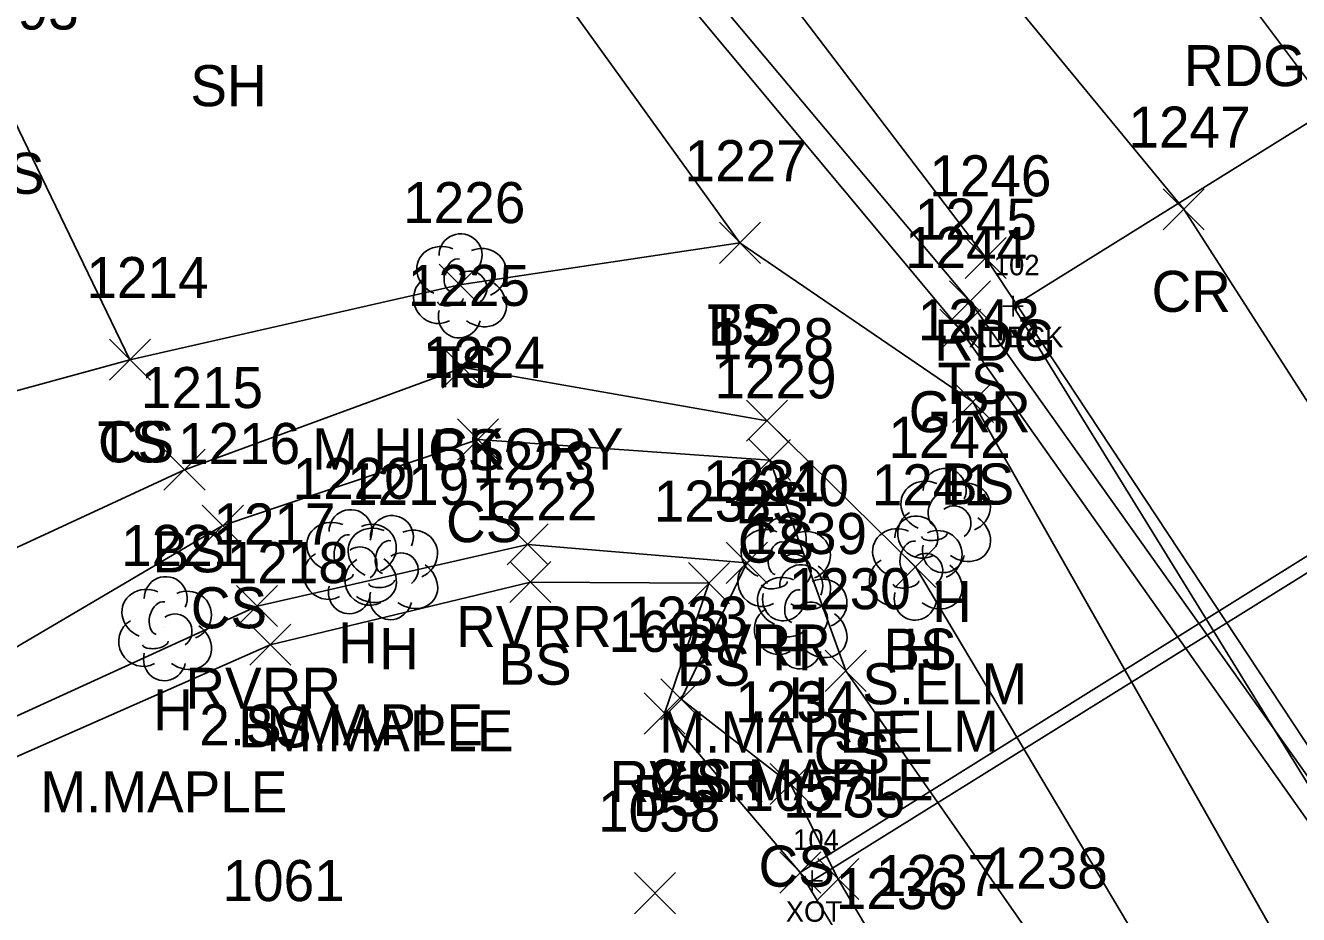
# Model space of a CAD drawing. Extents: x 1469310 to 1475157, y 493997 to 498873.
# Drawn here: x 1469498.4 to 1469560.4, y 498562.2 to 498605.4 of the extents above; entities that cross this region are included whole.
import ezdxf

# ---------------------------------------------------------------- set-up
doc = ezdxf.new("R2010")
doc.units = 0
for name, color, linetype in [('B_A', 7, 'Continuous'), ('B_I', 7, 'Continuous'), ('B_TIC', 7, 'Continuous'), ('BDEFAULT', 7, 'Continuous'), ('BELB', 7, 'Continuous'), ('D_I', 7, 'Continuous'), ('D_TIC', 7, 'Continuous'), ('DCP', 7, 'Continuous'), ('L_A', 7, 'Continuous'), ('L_C', 7, 'Continuous'), ('L_I', 7, 'Continuous'), ('L_TIC', 7, 'Continuous'), ('LAWE', 7, 'Continuous'), ('LELB', 7, 'Continuous'), ('LTD', 7, 'Continuous'), ('P_A', 7, 'Continuous'), ('P_I', 7, 'Continuous'), ('P_TIC', 7, 'Continuous'), ('PEU', 7, 'Continuous'), ('PRC', 7, 'Continuous'), ('R_A', 7, 'Continuous'), ('R_I', 7, 'Continuous'), ('R_TIC', 7, 'Continuous'), ('RGR', 7, 'Continuous')]:
    doc.layers.add(name, color=color, linetype=linetype)

msp = doc.modelspace()

# ---------------------------------------------------------------- linework, layer by layer
at = {"layer": 'B_TIC'}
for p, q in [((1469546.473, 498591.781), (1469546.549, 498591.781)), ((1469536.7, 498563.801), (1469536.776, 498563.801))]:
    msp.add_line(p, q, dxfattribs=at)
for points in [[(1469546.47, 498591.281), (1469546.47, 498592.281)], [(1469545.97, 498591.781), (1469546.97, 498591.781)], [(1469536.697, 498563.301), (1469536.697, 498564.301)], [(1469536.197, 498563.801), (1469537.197, 498563.801)]]:
    msp.add_lwpolyline(points, dxfattribs=at)
at = {"layer": 'BDEFAULT'}
msp.add_lwpolyline([(1469536.697, 498563.801), (1469602.369, 498604.653)], dxfattribs=at)
at = {"layer": 'BELB'}
msp.add_lwpolyline([(1469588.085, 498573.469), (1469568.345, 498605.383), (1469546.47, 498591.781), (1469566.105, 498559.964), (1469588.085, 498573.469)], dxfattribs=at)
at = {"layer": 'D_TIC'}
for points in [[(1469535.113, 498563.2), (1469537.113, 498565.2)], [(1469537.113, 498563.2), (1469535.113, 498565.2)]]:
    msp.add_lwpolyline(points, dxfattribs=at)
at = {"layer": 'DCP'}
msp.add_lwpolyline([(1469602.07, 498605.375), (1469536.113, 498564.2)], dxfattribs=at)
at = {"layer": 'L_TIC'}
for points in [[(1469532.172, 498593.862), (1469534.172, 498595.862)], [(1469534.172, 498593.862), (1469532.172, 498595.862)], [(1469532.172, 498593.862), (1469534.172, 498595.862)], [(1469534.172, 498593.862), (1469532.172, 498595.862)], [(1469518.522, 498591.822), (1469520.522, 498593.822)], [(1469520.522, 498591.822), (1469518.522, 498593.822)], [(1469543.375, 498591.02), (1469545.375, 498593.02)], [(1469545.375, 498591.02), (1469543.375, 498593.02)], [(1469502.469, 498588.172), (1469504.469, 498590.172)], [(1469504.469, 498588.172), (1469502.469, 498590.172)], [(1469502.469, 498588.172), (1469504.469, 498590.172)], [(1469504.469, 498588.172), (1469502.469, 498590.172)], [(1469518.691, 498587.789), (1469520.691, 498589.789)], [(1469520.691, 498587.789), (1469518.691, 498589.789)], [(1469543.52, 498586.119), (1469545.52, 498588.119)], [(1469545.52, 498586.119), (1469543.52, 498588.119)], [(1469533.493, 498585.197), (1469535.493, 498587.197)], [(1469535.493, 498585.197), (1469533.493, 498587.197)], [(1469519.418, 498584.286), (1469521.418, 498586.286)], [(1469521.418, 498584.286), (1469519.418, 498586.286)], [(1469533.627, 498583.287), (1469535.627, 498585.287)], [(1469535.627, 498583.287), (1469533.627, 498585.287)], [(1469505.126, 498582.816), (1469507.126, 498584.816)], [(1469507.126, 498582.816), (1469505.126, 498584.816)], [(1469506.99, 498580.091), (1469508.99, 498582.091)], [(1469508.99, 498580.091), (1469506.99, 498582.091)], [(1469521.838, 498579.179), (1469523.838, 498581.179)], [(1469523.838, 498579.179), (1469521.838, 498581.179)], [(1469532.507, 498578.279), (1469534.507, 498580.279)], [(1469534.507, 498578.279), (1469532.507, 498580.279)], [(1469540.719, 498578.078), (1469542.719, 498580.078)], [(1469542.719, 498578.078), (1469540.719, 498580.078)], [(1469521.971, 498577.343), (1469523.971, 498579.343)], [(1469523.971, 498577.343), (1469521.971, 498579.343)], [(1469530.664, 498577.288), (1469532.664, 498579.288)], [(1469532.664, 498577.288), (1469530.664, 498579.288)], [(1469508.656, 498576.171), (1469510.656, 498578.171)], [(1469510.656, 498576.171), (1469508.656, 498578.171)], [(1469509.304, 498574.289), (1469511.304, 498576.289)], [(1469511.304, 498574.289), (1469509.304, 498576.289)], [(1469537.322, 498573.02), (1469539.322, 498575.02)], [(1469539.322, 498573.02), (1469537.322, 498575.02)], [(1469529.314, 498571.636), (1469531.314, 498573.636)], [(1469531.314, 498571.636), (1469529.314, 498573.636)], [(1469529.314, 498571.636), (1469531.314, 498573.636)], [(1469531.314, 498571.636), (1469529.314, 498573.636)], [(1469528.504, 498570.943), (1469530.504, 498572.943)], [(1469530.504, 498570.943), (1469528.504, 498572.943)], [(1469534.638, 498567.508), (1469536.638, 498569.508)], [(1469536.638, 498567.508), (1469534.638, 498569.508)], [(1469535.113, 498563.2), (1469537.113, 498565.2)], [(1469537.113, 498563.2), (1469535.113, 498565.2)], [(1469536.962, 498562.876), (1469538.962, 498564.876)], [(1469538.962, 498562.876), (1469536.962, 498564.876)], [(1469528.036, 498562.191), (1469530.036, 498564.191)], [(1469530.036, 498562.191), (1469528.036, 498564.191)]]:
    msp.add_lwpolyline(points, dxfattribs=at)
at = {"layer": 'LAWE'}
msp.add_lwpolyline([(1469389.723, 498705.758), (1469405.142, 498682.895), (1469430.854, 498646.131), (1469451.62, 498613.535), (1469475.38, 498586.01), (1469482.321, 498572.691), (1469484.587, 498569.541), (1469489.264, 498567.845), (1469509.656, 498577.171), (1469522.838, 498580.179), (1469533.507, 498579.279), (1469530.314, 498572.636)], dxfattribs=at)
at = {"layer": 'LELB'}
for points in [[(1469416.823, 498734.314), (1469446.326, 498703.097), (1469470.885, 498677.648), (1469509.281, 498636.708), (1469524.422, 498615.805), (1469544.375, 498592.02), (1469564.878, 498563.16), (1469574.599, 498542.858), (1469576.567, 498532.675), (1469562.977, 498525.948), (1469548.2, 498517.369), (1469540.614, 498511.222), (1469554.066, 498484.991), (1469566.508, 498459.59)], [(1469413.419, 498730.944), (1469442.517, 498698.703), (1469468.453, 498674.773), (1469500.535, 498635.821), (1469519.003, 498614.534), (1469533.172, 498594.862), (1469544.52, 498587.119), (1469562.893, 498554.703), (1469567.788, 498543.524), (1469559.261, 498528.602), (1469545.395, 498521.66), (1469536.791, 498513.026)], [(1469407.359, 498725.914), (1469434.353, 498693.874), (1469460.137, 498667.417), (1469482.37, 498626.837), (1469497.148, 498602.251), (1469503.469, 498589.172)], [(1469403.958, 498707.897), (1469421.49, 498683.842), (1469442.275, 498655.574), (1469465.354, 498618.648), (1469483.42, 498593.573), (1469487.554, 498583.883), (1469493.167, 498586.365), (1469503.469, 498589.172), (1469519.522, 498592.822), (1469533.172, 498594.862)], [(1469387.884, 498704.334), (1469404.105, 498681.984), (1469428.903, 498644.42), (1469449.541, 498612.822), (1469474.412, 498585.158), (1469480.643, 498571.191), (1469484.925, 498567.971), (1469489.155, 498565.964), (1469510.304, 498575.289), (1469522.971, 498578.343), (1469531.664, 498578.288)], [(1469434.428, 498661.856), (1469439.868, 498652.509), (1469461.918, 498616.733), (1469481.608, 498592.394), (1469486.836, 498579.655), (1469494.023, 498578.216), (1469506.126, 498583.816), (1469519.691, 498588.789), (1469534.493, 498586.197), (1469541.719, 498579.078), (1469557.439, 498552.672)], [(1469428.533, 498658.897), (1469433.568, 498648.515), (1469459.288, 498614.436), (1469478.332, 498589.059), (1469483.968, 498576.627), (1469489.341, 498572.759), (1469492.494, 498571.977), (1469507.99, 498581.091), (1469520.418, 498585.286), (1469534.627, 498584.287), (1469538.322, 498574.02), (1469547.828, 498560.419), (1469557.439, 498552.672), (1469555.667, 498535.666), (1469539.848, 498524.73), (1469536.791, 498513.026), (1469549.045, 498482.48), (1469564.461, 498458.053), (1469576.503, 498438.755), (1469578.882, 498431.595)], [(1469529.504, 498571.943), (1469531.664, 498578.288)], [(1469530.314, 498572.636), (1469535.638, 498568.508), (1469537.962, 498563.876), (1469540.583, 498559.415), (1469541.729, 498555.03)], [(1469536.113, 498564.2), (1469529.504, 498571.943)], [(1469542.737, 498553.271), (1469536.113, 498564.2)]]:
    msp.add_lwpolyline(points, dxfattribs=at)
at = {"layer": 'LTD'}
for p, q in [((1469519.522, 498592.822), (1469519.522, 498592.822)), ((1469519.522, 498592.822), (1469519.522, 498592.822)), ((1469543.097, 498581.391), (1469543.097, 498581.391)), ((1469543.097, 498581.391), (1469543.097, 498581.391)), ((1469514.168, 498579.389), (1469514.168, 498579.389)), ((1469514.168, 498579.389), (1469514.168, 498579.389)), ((1469516.177, 498579.1), (1469516.177, 498579.1)), ((1469516.177, 498579.1), (1469516.177, 498579.1)), ((1469535.31, 498579.041), (1469535.31, 498579.041)), ((1469535.31, 498579.041), (1469535.31, 498579.041)), ((1469541.719, 498579.078), (1469541.719, 498579.078)), ((1469541.719, 498579.078), (1469541.719, 498579.078)), ((1469536.112, 498576.707), (1469536.112, 498576.707)), ((1469536.112, 498576.707), (1469536.112, 498576.707)), ((1469505.163, 498576.126), (1469505.163, 498576.126)), ((1469505.163, 498576.126), (1469505.163, 498576.126))]:
    msp.add_line(p, q, dxfattribs=at)
for centre in [(1469519.569, 498594.256), (1469543.144, 498582.825), (1469514.215, 498580.823), (1469516.224, 498580.534), (1469535.357, 498580.475), (1469541.766, 498580.512), (1469536.159, 498578.141), (1469505.21, 498577.56)]:
    msp.add_arc(centre, 1.047, 335.52715, 180.95627, dxfattribs=at)
for centre, major_axis, ratio, start_param, end_param in [((1469518.73, 498593.488), (1.21, -0.512), 0.895232, 1.570796, 4.712389), ((1469520.564, 498593.405), (-1.141, -0.483), 0.949671, 1.570796, 4.712389), ((1469519.314, 498593.28), (-0.208, -0.792), 0.645439, 3.141593, 6.283185), ((1469518.439, 498592.113), (0.584, -1.042), 0.959034, 3.141593, 6.283185), ((1469520.022, 498592.655), (-0.5, 0.667), 0.989748, 3.141593, 6.283185), ((1469520.522, 498591.989), (-1.09, 0.792), 0.841452, 1.570796, 4.712389), ((1469519.064, 498592.072), (-0.625, -0.083), 0.423636, 0, 3.141593), ((1469519.522, 498591.322), (0.265, 1.061), 0.942809, 1.570796, 4.712389), ((1469542.305, 498582.058), (1.21, -0.512), 0.895232, 1.570796, 4.712389), ((1469544.139, 498581.975), (-1.141, -0.483), 0.949671, 1.570796, 4.712389), ((1469542.889, 498581.849), (-0.208, -0.792), 0.645439, 3.141593, 6.283185), ((1469543.597, 498581.224), (-0.5, 0.667), 0.989748, 3.141593, 6.283185), ((1469513.376, 498580.055), (1.21, -0.512), 0.895232, 1.570796, 4.712389), ((1469515.209, 498579.972), (-1.141, -0.483), 0.949671, 1.570796, 4.712389), ((1469542.014, 498580.682), (0.584, -1.042), 0.959034, 3.141593, 6.283185), ((1469544.097, 498580.558), (-1.09, 0.792), 0.841452, 1.570796, 4.712389), ((1469513.959, 498579.847), (-0.208, -0.792), 0.645439, 3.141593, 6.283185), ((1469515.385, 498579.767), (1.21, -0.512), 0.895232, 1.570796, 4.712389), ((1469517.218, 498579.684), (-1.141, -0.483), 0.949671, 1.570796, 4.712389), ((1469534.518, 498579.708), (1.21, -0.512), 0.895232, 1.570796, 4.712389), ((1469536.352, 498579.625), (-1.141, -0.483), 0.949671, 1.570796, 4.712389), ((1469540.927, 498579.745), (1.21, -0.512), 0.895232, 1.570796, 4.712389), ((1469542.639, 498580.641), (-0.625, -0.083), 0.423636, 0, 3.141593), ((1469542.76, 498579.662), (-1.141, -0.483), 0.949671, 1.570796, 4.712389), ((1469514.668, 498579.222), (-0.5, 0.667), 0.989748, 3.141593, 6.283185), ((1469515.969, 498579.559), (-0.208, -0.792), 0.645439, 3.141593, 6.283185), ((1469535.102, 498579.5), (-0.208, -0.792), 0.645439, 3.141593, 6.283185), ((1469541.51, 498579.537), (-0.208, -0.792), 0.645439, 3.141593, 6.283185), ((1469543.097, 498579.891), (0.265, 1.061), 0.942809, 1.570796, 4.712389), ((1469513.085, 498578.68), (0.584, -1.042), 0.959034, 3.141593, 6.283185), ((1469515.168, 498578.556), (-1.09, 0.792), 0.841452, 1.570796, 4.712389), ((1469516.677, 498578.934), (-0.5, 0.667), 0.989748, 3.141593, 6.283185), ((1469535.81, 498578.875), (-0.5, 0.667), 0.989748, 3.141593, 6.283185), ((1469542.219, 498578.912), (-0.5, 0.667), 0.989748, 3.141593, 6.283185), ((1469515.094, 498578.392), (0.584, -1.042), 0.959034, 3.141593, 6.283185), ((1469517.177, 498578.267), (-1.09, 0.792), 0.841452, 1.570796, 4.712389), ((1469534.227, 498578.333), (0.584, -1.042), 0.959034, 3.141593, 6.283185), ((1469536.31, 498578.208), (-1.09, 0.792), 0.841452, 1.570796, 4.712389), ((1469540.636, 498578.37), (0.584, -1.042), 0.959034, 3.141593, 6.283185), ((1469542.719, 498578.245), (-1.09, 0.792), 0.841452, 1.570796, 4.712389), ((1469513.71, 498578.639), (-0.625, -0.083), 0.423636, 0, 3.141593), ((1469515.719, 498578.35), (-0.625, -0.083), 0.423636, 0, 3.141593), ((1469535.32, 498577.374), (1.21, -0.512), 0.895232, 1.570796, 4.712389), ((1469534.852, 498578.291), (-0.625, -0.083), 0.423636, 0, 3.141593), ((1469537.154, 498577.291), (-1.141, -0.483), 0.949671, 1.570796, 4.712389), ((1469541.261, 498578.328), (-0.625, -0.083), 0.423636, 0, 3.141593), ((1469504.372, 498576.792), (1.21, -0.512), 0.895232, 1.570796, 4.712389), ((1469506.205, 498576.709), (-1.141, -0.483), 0.949671, 1.570796, 4.712389), ((1469514.168, 498577.889), (0.265, 1.061), 0.942809, 1.570796, 4.712389), ((1469516.177, 498577.6), (0.265, 1.061), 0.942809, 1.570796, 4.712389), ((1469535.31, 498577.541), (0.265, 1.061), 0.942809, 1.570796, 4.712389), ((1469535.904, 498577.166), (-0.208, -0.792), 0.645439, 3.141593, 6.283185), ((1469541.719, 498577.578), (0.265, 1.061), 0.942809, 1.570796, 4.712389), ((1469504.955, 498576.584), (-0.208, -0.792), 0.645439, 3.141593, 6.283185), ((1469535.029, 498575.999), (0.584, -1.042), 0.959034, 3.141593, 6.283185), ((1469536.612, 498576.541), (-0.5, 0.667), 0.989748, 3.141593, 6.283185), ((1469504.08, 498575.417), (0.584, -1.042), 0.959034, 3.141593, 6.283185), ((1469505.663, 498575.959), (-0.5, 0.667), 0.989748, 3.141593, 6.283185), ((1469537.112, 498575.874), (-1.09, 0.792), 0.841452, 1.570796, 4.712389), ((1469506.164, 498575.293), (-1.09, 0.792), 0.841452, 1.570796, 4.712389), ((1469535.654, 498575.957), (-0.625, -0.083), 0.423636, 0, 3.141593), ((1469504.705, 498575.376), (-0.625, -0.083), 0.423636, 0, 3.141593), ((1469536.112, 498575.207), (0.265, 1.061), 0.942809, 1.570796, 4.712389), ((1469505.164, 498574.626), (0.265, 1.061), 0.942809, 1.570796, 4.712389)]:
    msp.add_ellipse(centre, major_axis=major_axis, ratio=ratio, start_param=start_param, end_param=end_param, dxfattribs=at)
at = {"layer": 'P_TIC'}
for points in [[(1469553.784, 498595.501), (1469555.784, 498597.501)], [(1469555.784, 498595.501), (1469553.784, 498597.501)], [(1469544.139, 498593.127), (1469546.139, 498595.127)], [(1469546.139, 498593.127), (1469544.139, 498595.127)]]:
    msp.add_lwpolyline(points, dxfattribs=at)
at = {"layer": 'PEU'}
for points in [[(1469787.287, 498391.186), (1469770.786, 498403.186), (1469744.942, 498420.511), (1469711.225, 498443.774), (1469680.07, 498463.208), (1469651.576, 498483.407), (1469630.626, 498501.518), (1469612.52, 498523.24), (1469599.406, 498542.19), (1469591.57, 498556.602), (1469575.608, 498583.062), (1469557.307, 498607.493), (1469540.085, 498628.651), (1469536.237, 498634.985), (1469514.981, 498658.506), (1469490.833, 498684.266), (1469472.689, 498702.569), (1469444.888, 498732.157), (1469424.966, 498753.74), (1469411.282, 498767.744), (1469386.832, 498794.065), (1469360.465, 498820.438)], [(1469418.156, 498735.543), (1469447.908, 498704.219), (1469471.825, 498679.031), (1469509.9, 498637.995), (1469529.399, 498614.803), (1469545.139, 498594.127), (1469565.651, 498563.085), (1469576.412, 498543.24), (1469581.129, 498534.677), (1469591.748, 498510.077), (1469602.71, 498485.38), (1469609.033, 498458.441), (1469615.466, 498438.565), (1469621.976, 498404.809), (1469621.719, 498400.421), (1469625.378, 498362.571), (1469626.198, 498333.717)]]:
    msp.add_lwpolyline(points, dxfattribs=at)
at = {"layer": 'PRC'}
msp.add_lwpolyline([(1469423.494, 498741.591), (1469452.569, 498710.453), (1469477.957, 498685.461), (1469512.008, 498647.602), (1469532.7, 498623.323), (1469554.784, 498596.501), (1469570.656, 498571.785), (1469585.254, 498547.179), (1469603.312, 498509.955), (1469610.701, 498488.938), (1469623.702, 498439.145), (1469630.721, 498407.825), (1469631.037, 498401.913), (1469634.459, 498363.902), (1469634.516, 498333.309)], dxfattribs=at)
at = {"layer": 'R_TIC'}
for points in [[(1469542.903, 498589.637), (1469544.903, 498591.637)], [(1469544.903, 498589.637), (1469542.903, 498591.637)]]:
    msp.add_lwpolyline(points, dxfattribs=at)
at = {"layer": 'RGR'}
msp.add_lwpolyline([(1469523.975, 498614.546), (1469543.903, 498590.637), (1469565.017, 498560.783), (1469572.552, 498542.581)], dxfattribs=at)

# ---------------------------------------------------------------- texts
at = {"layer": 'B_A'}
for s, p in [('XDECK', (1469544.312, 498589.781)), ('XOT', (1469535.402, 498561.801))]:
    msp.add_text(s, height=1, dxfattribs=at).set_placement(p)
at = {"layer": 'B_I'}
for s, p in [('102', (1469545.533, 498593.281)), ('104', (1469535.76, 498565.301))]:
    msp.add_text(s, height=1, dxfattribs=at).set_placement(p)
at = {"layer": 'D_I'}
msp.add_text('1057', height=2, dxfattribs=at).set_placement((1469533.341, 498567.2))
at = {"layer": 'L_A'}
for s, p in [('SH', (1469506.41, 498601.516)), ('CS', (1469495.589, 498597.251)), ('TS', (1469531.581, 498589.862)), ('BS', (1469531.613, 498589.862)), ('TS', (1469517.932, 498587.822)), ('H', (1469518.955, 498587.822)), ('TS', (1469542.784, 498587.02)), ('TS', (1469501.879, 498584.172)), ('CS', (1469501.91, 498584.172)), ('BS', (1469518.132, 498583.789)), ('BS', (1469542.961, 498582.119)), ('BS', (1469532.934, 498581.197)), ('CS', (1469518.859, 498580.286)), ('CS', (1469533.068, 498579.287)), ('BS', (1469504.567, 498578.816)), ('H', (1469542.53, 498576.391)), ('CS', (1469506.431, 498576.091)), ('RVRR', (1469519.349, 498575.179)), ('H', (1469513.601, 498574.389)), ('H', (1469515.61, 498574.1)), ('RVRR', (1469530.019, 498574.279)), ('H', (1469534.743, 498574.041)), ('BS', (1469540.16, 498574.078)), ('H', (1469541.152, 498574.078)), ('BS', (1469521.412, 498573.343)), ('BS', (1469530.105, 498573.288)), ('RVRR', (1469506.168, 498572.171)), ('H', (1469535.545, 498571.707)), ('H', (1469504.597, 498571.126)), ('BS', (1469508.745, 498570.289)), ('CS', (1469536.763, 498569.02)), ('RVRR', (1469526.826, 498567.636)), ('CS', (1469528.755, 498567.636)), ('BS', (1469527.945, 498566.943)), ('CS', (1469534.079, 498563.508))]:
    msp.add_text(s, height=2, dxfattribs=at).set_placement(p)
at = {"layer": 'L_C'}
for s, p in [('M.HICKORY', (1469512.341, 498583.822)), ('S.ELM', (1469539.129, 498572.391)), ('2.S.MAPLE', (1469506.845, 498570.389)), ('M.MAPLE', (1469510.114, 498570.1)), ('M.MAPLE', (1469529.247, 498570.041)), ('S.ELM', (1469537.75, 498570.078)), ('2.S.MAPLE', (1469528.789, 498567.707)), ('M.MAPLE', (1469499.101, 498567.126))]:
    msp.add_text(s, height=2, dxfattribs=at).set_placement(p)
at = {"layer": 'L_I'}
for s, p in [('1193', (1469495.022, 498605.251)), ('1227', (1469530.479, 498597.862)), ('1227', (1469530.479, 498597.862)), ('1226', (1469516.774, 498595.822)), ('1226', (1469516.774, 498595.822)), ('1245', (1469541.682, 498595.02)), ('1214', (1469501.344, 498592.172)), ('1214', (1469501.344, 498592.172)), ('1225', (1469516.998, 498591.789)), ('1243', (1469541.828, 498590.119)), ('1228', (1469531.801, 498589.197)), ('1224', (1469517.725, 498588.286)), ('1215', (1469504, 498586.816)), ('1229', (1469531.927, 498587.287)), ('1242', (1469540.404, 498584.391)), ('1216', (1469505.809, 498584.091)), ('1223', (1469520.145, 498583.179)), ('1220', (1469511.389, 498582.389)), ('1219', (1469514.043, 498582.1)), ('1231', (1469531.382, 498582.279)), ('1240', (1469532.531, 498582.041)), ('1241', (1469539.593, 498582.078)), ('1241', (1469539.593, 498582.078)), ('1222', (1469520.279, 498581.343)), ('1232', (1469528.971, 498581.288)), ('1217', (1469507.53, 498580.171)), ('1239', (1469533.412, 498579.707)), ('1221', (1469503.038, 498579.126)), ('1218', (1469508.178, 498578.289)), ('1230', (1469535.543, 498577.02)), ('1233', (1469527.621, 498575.636)), ('1233', (1469527.621, 498575.636)), ('1693', (1469526.764, 498574.943)), ('1234', (1469532.945, 498571.508)), ('1057', (1469533.341, 498567.2)), ('1235', (1469535.269, 498566.876)), ('1058', (1469526.265, 498566.191)), ('1238', (1469545.136, 498563.419)), ('1238', (1469545.136, 498563.419)), ('1061', (1469507.978, 498562.805)), ('1237', (1469539.789, 498563.056)), ('1236', (1469537.835, 498562.415)), ('1236', (1469537.835, 498562.415))]:
    msp.add_text(s, height=2, dxfattribs=at).set_placement(p)
at = {"layer": 'P_A'}
for s, p in [('RDG', (1469554.795, 498602.493)), ('CR', (1469553.217, 498591.501)), ('RDG', (1469542.627, 498589.127))]:
    msp.add_text(s, height=2, dxfattribs=at).set_placement(p)
at = {"layer": 'P_I'}
for s, p in [('1247', (1469552.091, 498599.501)), ('1246', (1469542.391, 498597.127))]:
    msp.add_text(s, height=2, dxfattribs=at).set_placement(p)
at = {"layer": 'R_A'}
msp.add_text('GRR', height=2, dxfattribs=at).set_placement((1469541.391, 498585.637))
at = {"layer": 'R_I'}
msp.add_text('1244', height=2, dxfattribs=at).set_placement((1469541.21, 498593.637))

doc.saveas('drawing.dxf')
